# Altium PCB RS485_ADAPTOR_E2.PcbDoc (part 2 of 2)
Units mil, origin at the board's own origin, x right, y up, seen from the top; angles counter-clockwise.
Board outline 2150 x 1600 mil, 2 copper layers (Top Layer, Bottom Layer), stack 62 mil thick; 112 components, 44 nets, 256 pads, 64 vias.
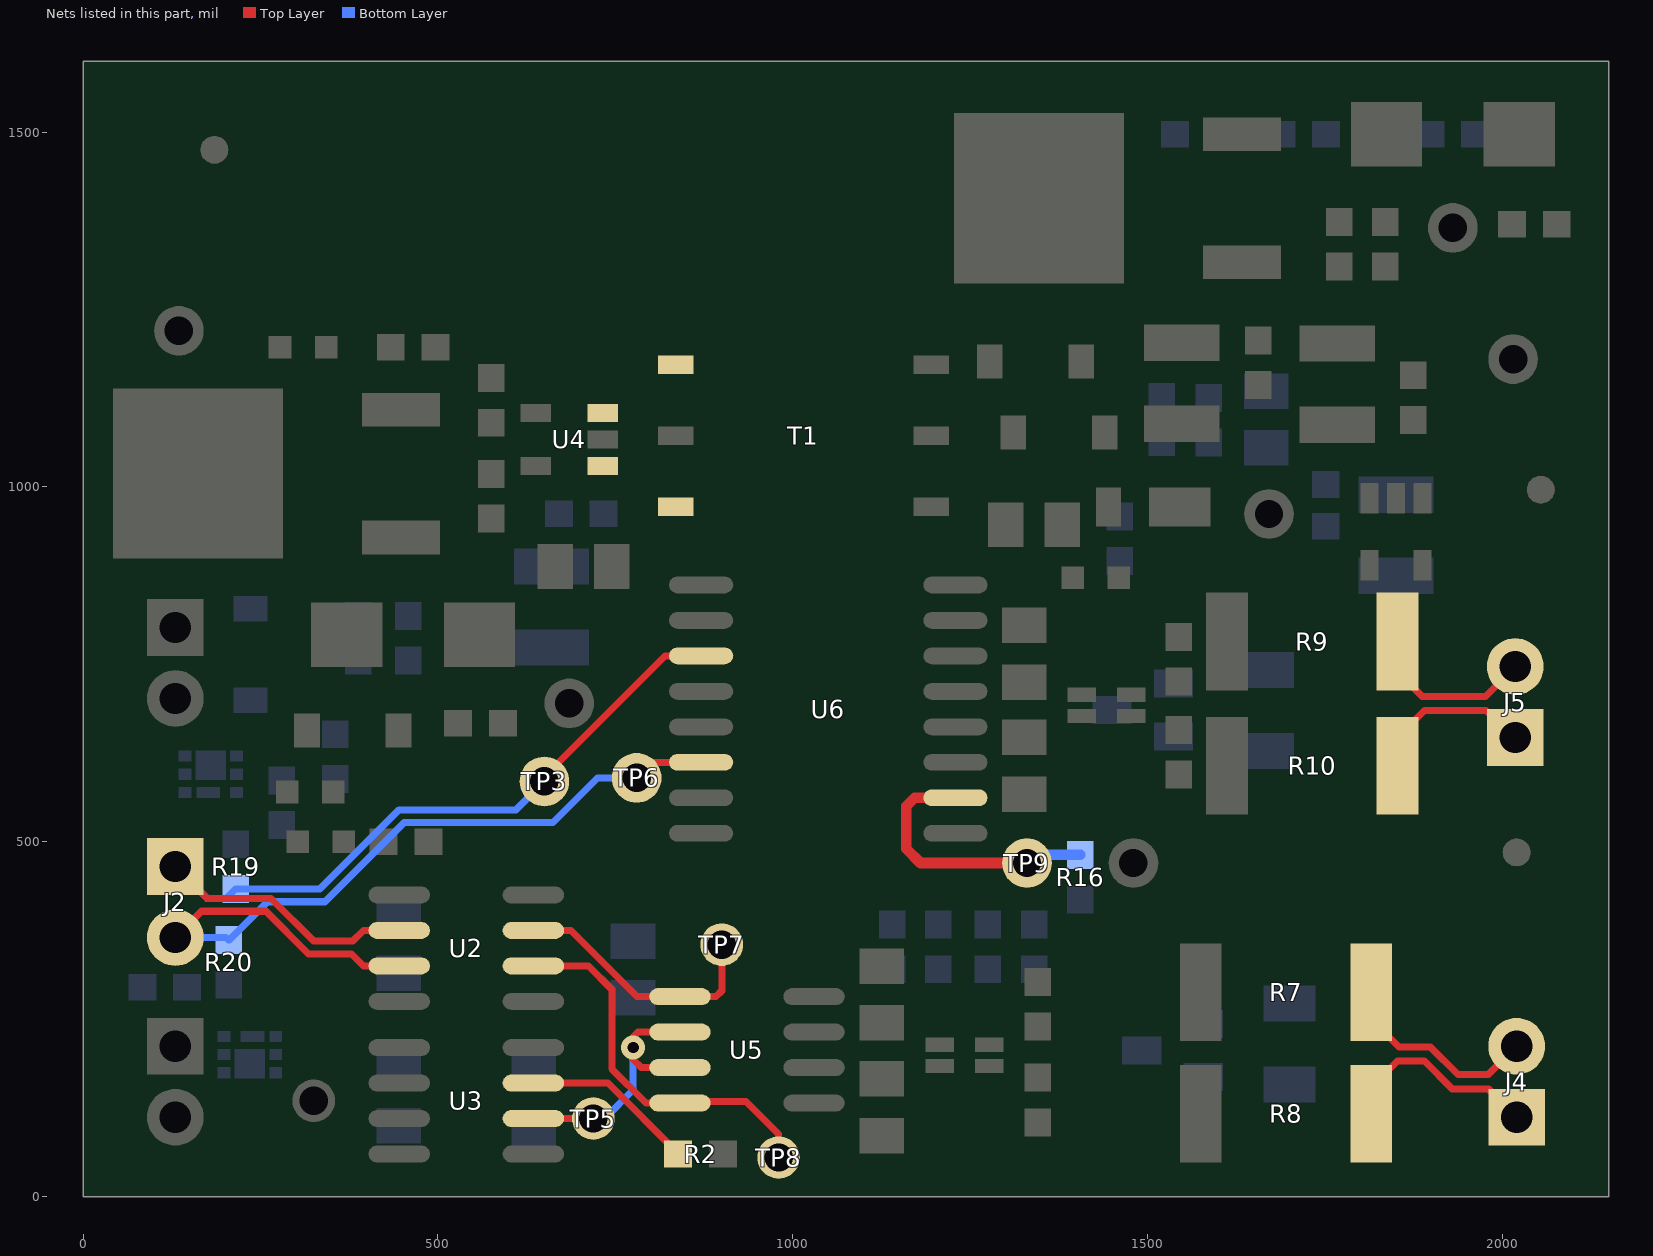
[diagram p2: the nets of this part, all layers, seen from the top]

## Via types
v1: diameter 34, hole 16, Top Layer to Bottom Layer, tented both sides, 64 vias

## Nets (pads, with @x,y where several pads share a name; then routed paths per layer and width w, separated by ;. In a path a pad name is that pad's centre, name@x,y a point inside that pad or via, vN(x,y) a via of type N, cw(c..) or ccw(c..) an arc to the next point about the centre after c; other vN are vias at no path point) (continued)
NetJ4_1: J4.1 R8.2 | length 298.3
  Top Layer w10: R8.2@1795.08,116.85 1795.08,133.93 1852,190.85 1890,190.85 1929,151.85 1980,151.85 J4.1@2020,111.85
NetJ4_2: J4.2 R7.2 | length 300.3
  Top Layer w10: R7.2@1795.08,287.85 1795.08,269.77 1854,210.85 1898.28,210.85 1937.28,171.85 1980,171.85 J4.2@2020,211.85
  Bottom Layer w10: J4.2@2019.91,211.76 J4.2@2020,211.85
NetJ5_1: J5.1 R10.2 | length 238.2
  Top Layer w10: R10.2@1852.08,607 1851,608.08 1851,645.85 1890,684.85 1977,684.85 J5.1@2015,646.85
  Bottom Layer w10: J5.1@2015,646.85 J5.1@2018,646.85
NetJ5_2: J5.2 R9.2 | length 240
  Top Layer w10: R9.2@1852.08,782 1852.08,739.77 1887,704.85 1976,704.85 J5.2@2018,746.85
NetR2_2: R2.2 U3.7 | length 246
  Top Layer w10: U3.7@634.49,160 739.54,160 838.5,61.04 R2.2@838.5,60
NetR16_1: R16.1 TP9.1 U6.10 | length 392.1
  Top Layer w15: U6.10@1229.13,561.85 1171.85,561.85 1160,550 1160,490 1180,470 TP9.1@1330,470
  Bottom Layer w15: TP9.1@1330,470 1341.5,481.5 R16.1@1405,481.5
NetT1_1: T1.1 U4.3
NetT1_3: T1.3 U4.1
NetTP5_1: TP5.1 U3.6 U5.2 U5.3 | length 388.4
  Top Layer w10: U3.6@634.49,110 TP5.1@703,110 ; U5.3@841.01,181.85 786.42,181.85 775,193.27 v1(775,210) 775,225 781.85,231.85 U5.2@841.01,231.85
  Bottom Layer w10: TP5.1@703,110 735,110 775,150 v1(775,210)
NetTP7_1: TP7.1 U2.7 U5.1 | length 372.5
  Top Layer w10: U2.7@634.49,375 687.57,375 780.72,281.85 U5.1@841.01,281.85 891.85,281.85 900,290 TP7.1@900,355
NetTP8_1: TP8.1 U2.6 U5.4 | length 544.1
  Top Layer w10: U2.6@634.49,325 712.12,325 745,292.12 745,180 793.15,131.85 U5.4@841.01,131.85 843.16,134 934,134 980,88 TP8.1@980,55
RX: J2.1 R19.1 TP3.1 U2.2 U6.3 | length 1270.3
  Top Layer w10: J2.1@130,465 175,420 265,420 325,360 380,360 395,375 U2.2@445.51,375 ; TP3.1@650,585 650,591.85 820,761.85 U6.3@870.87,761.85
  Bottom Layer w10: J2.1@130,465 175,420 201.5,420 R19.1@215,433.5 333.5,433.5 445,545 610,545 TP3.1@650,585
TX: J2.2 R20.1 TP6.1 U2.3 U6.6 | length 1208.7
  Top Layer w10: J2.2@130,365 167,402 257.54,402 317.54,342 378,342 395,325 U2.3@445.51,325 ; TP6.1@780,590 801.85,611.85 U6.6@870.87,611.85
  Bottom Layer w10: J2.2@130,365 201.5,365 R20.1@205,361.5 205.99,361.5 260,415.5 340.96,415.5 452.46,527 662,527 725,590 TP6.1@780,590
pads on no net: FID1.1 FID2.1 FID3.1 FID4.1 FID5.1 FID6.1 LBL1.0 U3.2 U6.11 U6.14 U8.4 U8.5

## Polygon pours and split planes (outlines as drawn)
GND_VDC on Top Layer "Bottom Layer-No Net" (solid, remove dead copper, pour order 45): 1375,1175 1605,1175 1615,1185 1710,1185 1720,1175 1810,1175 1840,1145 1920,1145 1940,1165 1940,1220 1930,1230 1565,1230 1555,1240 1555,1555 1545,1565 1215,1565 1200,1550 1200,1050 1260,1050 1280,1070 1280,1105 1290,1115 1340,1115 1350,1105 1350,1050 1325,1025 1325,995 1335,985 1410,985 1425,1000 1425,1035 1370,1170
DGND on Top Layer "Bottom Layer-No Net" (solid, remove dead copper, pour order 30): 295,1270 280,1285 50,1285 40,1275 40,789.85 69,760.85 164,760.85 180,745 190,735 190,660 165,635 90,635 70,615 70,570 85,555 210,555 220,565 220,640 250,670 290,670 315,645 320,645 380,705 465,705 475,715 475,815 460,830 360.73,830 285,905 285,1160 295,1170
NetC3_1 on Top Layer "Bottom Layer-No Net" (solid, remove dead copper, pour order 32): 477,1151.85 467,1141.85 398,1141.85 390,1133.85 390,1064.85 404,1050.85 517,1050.85 539,1028.85 539,1010.85 553,996.85 593,996.85 595,998.85 595,1110.85 593,1112.85 546,1112.85 524,1134.85 524,1213.85 517,1220.85 480,1220.85 477,1217.85
DGND on Top Layer "Bottom Layer-No Net" (solid, remove dead copper, pour order 34): 662,1200.85 571,1200.85 553,1182.85 553,1135.85 556,1132.85 602,1132.85 616,1118.85 616,1002.85 622,996.85 648,996.85 690,1038.85 690,1172.85
DGND on Top Layer "Bottom Layer-No Net" (solid, remove dead copper, pour order 38): 616,960.85 638,938.85 638,857.85 640,855.85 690,855.85 694,859.85 694,926.85 682,938.85 682,1041.85 660,1063.85 624,1063.85 616,1055.85
DVCC on Top Layer "Bottom Layer-No Net" (solid, remove dead copper, pour order 39): 704,833 720,849 720,926 726,932 771,932 771,871 782,860 782,826 724,768 724,682 701,659 667,659 640,686 640,720 617,743 574,743 539.5,777.5 558,796 558,833
+5V on Top Layer "Bottom Layer-No Net" (solid, remove dead copper, pour order 41): 379,952.85 369,942.85 369,862.85 380,851.85 502,851.85 522,871.85 522,938.85 508,952.85
DVCC on Top Layer "Bottom Layer-No Net" (solid, remove dead copper, pour order 33): 551.46,974.85 541,964.39 541,869.85 498,826.85 498,690.85 484,676.85 424,676.85 424,573.85 433,564.85 546,564.85 556,574.85 556,711.85 616,771.85 616,919.85 593,942.85 593,974.85
NetT1_3 on Top Layer "Bottom Layer-No Net" (solid, remove dead copper, pour order 37): 710,1041.85 710,966.85 735,941.85 857,941.85 860,944.85 860,982.85 858,984.85 774,984.85 748,1010.85 748,1041.85
NetT1_1 on Top Layer "Bottom Layer-No Net" (solid, remove dead copper, pour order 36): 711,1092.85 711,1125.85 778,1192.85 791,1205.85 849,1205.85 858,1196.85 860,1194.85 860,1162.85 860,1158.85 858,1156.85 851,1149.85 835,1149.85 786,1149.85 755,1118.85 754,1117.85 754,1092.85
+5V on Top Layer "Bottom Layer-No Net" (solid, remove dead copper, pour order 35): 750,1078.85 758,1078.85 770,1090.85 778,1098.85 791,1098.85 847,1098.85 860,1085.85 860,1061.85 860,1056.85 853,1049.85 843,1039.85 842,1038.85 818,1038.85 818,1037.85 796,1015.85 794,1013.85 777,1013.85 776,1013.85 768,1021.85 767,1022.85 767,1031.85 767,1043.85 756,1054.85 755,1055.85 748,1055.85 743.24,1055.85 733.24,1065.85 733,1066.09 733,1075.3 733,1076.85 735,1078.85
NetD5_2 on Top Layer "Bottom Layer-No Net" (solid, remove dead copper, pour order 42): 1179,1202.85 1168,1191.85 1168,1158.85 1176,1150.85 1294,1150.85 1303,1159.85 1303,1193.85 1294,1202.85
NetD7_2 on Top Layer "Bottom Layer-No Net" (solid, remove dead copper, pour order 43): 1207,985.85 1291,1069.85 1291,1101.85 1295,1105.85 1328,1105.85 1332,1101.85 1332,1049.85 1281,998.85 1264,998.85 1253,987.85 1253,948.85 1229,924.85 1181,924.85 1166,939.85 1166,983.85 1168,985.85
GND_VDC on Top Layer "Bottom Layer-No Net" (solid, remove dead copper, pour order 47): 1344,1031.85 1330,1017.85 1330,1003.85 1355,978.85 1355,895.85 1304,844.85 1304,784.85 1477,784.85 1491,770.85 1530,770.85 1530,809.85 1500,839.85 1427,839.85 1427,930.85 1442,945.85 1465,945.85 1469,949.85 1469,998.85 1447,1020.85 1416,1020.85 1405,1031.85
NetC18_2 on Top Layer "Bottom Layer-No Net" (solid, remove dead copper, pour order 49): 1811,1005.85 1750,1005.85 1717,972.85 1717,882.85 1719,880.85 1730,869.85 1744,869.85 1762,869.85 1769,876.85 1770,877.85 1770,886.85 1770,952.85 1780,962.85 1802,962.85 1814,962.85 1822,970.85 1822,1001.85 1818,1005.85
+6V_VDC on Top Layer "Bottom Layer-No Net" (solid, remove dead copper, pour order 44): 1387,1201.85 1384,1198.85 1384,1140.85 1417,1107.85 1417,1051.85 1425,1043.85 1455,1043.85 1471.08,1059.93 1609.06,1059.73 1642,1092.85 1667,1092.85 1724,1035.85 1815,1035.85 1837,1013.85 1837,962.85 1860,965 1860,1025 1900,1065 2040,1065 2050,1075 2050,1285 2035,1300 1885,1300 1865,1320 1720,1320 1695,1345 1580,1345 1580,1255 1595,1240 1960,1240 1980,1220 1980,1125 1970,1115 1725,1115 1675,1165 1625,1165 1585,1125 1480,1125 1427,1177.85 1427,1198.85 1424,1201.85
NetC20_1 on Top Layer "Bottom Layer-No Net" (solid, remove dead copper, pour order 46): 1585,1525 1585,1415 1595,1405 1650,1405 1685,1405 1690,1410 1705,1425 1705,1495 1705,1525 1695,1535 1605,1535 1595,1535 1585,1525
+5.0V_VDC on Top Layer "Bottom Layer-No Net" (solid, remove dead copper, pour order 57): 1559,615 1559,557 1505,515 1460,515 1450,505 1450,365 1435,350 1435,250 1420,235 1360,235 1350,245 1350,370 1385,405 1385,550 1400,565 1463,565 1490,594 1490,615
GND_VDC on Bottom Layer "Bottom Layer-No Net" (solid, remove dead copper, pour order 58): 2095,1555 2085,1565 1950,1565 1940,1555 1940,1460 1930,1450 1705,1450 1640,1385 1560,1385 1545,1400 1545,1550 1535,1560 1365,1560 1320,1515 1320,1000 1325,995 1400,995 1405,1000 1405,1330 1430,1355 2080,1355 2095,1370
+5.0V_VDC on Bottom Layer "Bottom Layer-No Net" (solid, remove dead copper, pour order 48): 1225,975 1210,960 1210,860 1257,849.85 1280,849.85 1335,905 1400,905 1435,940 1480,940 1485,945 1625,945 1630,950 1630,1015 1625,1020 1610,1020 1595,1005 1495,1005 1485,1015 1485,1100 1495,1110 1535,1110 1540,1115 1540,1195 1605,1260 2100,1260 2110,1270 2110,1315 2095,1330 1480,1330 1430,1280 1430,1000 1405,975
DGND on Bottom Layer "Bottom Layer-No Net" (solid, remove dead copper, pour order 55): 560,770 595,805 790,805 830,845 830,1155 815,1170 715,1170 695,1150 695,955 685,945 640,945 635,950 635,1155 605,1185 55,1185 45,1195 45,1280 55,1290 865,1290 890,1265 890,520 875,505 705,505 700,510 700,620 685,635 645,635 605,595 575,595 490,680 295,680 285,690 285,740 290,745 335,745 360,770
+5.0V_VDC on Bottom Layer "Bottom Layer-No Net" (solid, remove dead copper, pour order 52): 1218,955.85 1209,946.85 1209,563.85 1255,517.85 1372,517.85 1372,541.85 1308,605.85 1308,910.85 1263,955.85
NetC19_2 on Bottom Layer "Bottom Layer-No Net" (solid, remove dead copper, pour order 51): 1765,985 1735,985 1710,1010 1695,1025 1620,1025 1515,1025 1500,1040 1500,1080 1540,1080 1735,1080 1770,1045 1770,990 1765,985
NetC18_2 on Bottom Layer "Bottom Layer-No Net" (solid, pour order 50): 1773,962.85 1776,959.85 1776,918.85 1793,901.85 1903,901.85 1907,897.85 1907,839.85 1893,825.85 1768,825.85 1730,863.85 1730,962.85
GND_VDC on Bottom Layer "Bottom Layer-No Net" (solid, remove dead copper, pour order 54): 1590,1220 1605,1235 1960,1235 1995,1200 1995,1050 1915,970 1810,970 1800,980 1800,1040 1735,1105 1600,1105 1590,1115
+5.0V_VDC on Bottom Layer "Bottom Layer-No Net" (solid, remove dead copper, pour order 56): 645,405 635,395 635,150 705,150 735,180 735,235 730,240 690,240 685,245 685,305 705,325 820,325 830,315 830,295 880,245 1310,245 1320,235 1320,100 1330,90 1405,90 1420,105 1420,340 1415,345 865,345 805,405
NetD11_2 on Bottom Layer "Bottom Layer-No Net" (solid, remove dead copper, pour order 31): 76,649 180,649 197,666 197,732 180,751 81,751 65,735 65,660
+5V on Bottom Layer "Bottom Layer-No Net" (solid, remove dead copper, pour order 40): 209,807 356,807 360,802 362.46,797.85 528,797.85 592,861.85 761,861.85 809,909.85 809,1087.48 793.63,1102.85 729,1102.85 715,1088.85 715,1060.85 715,1053.85 715,936.85 701,922.85 382,922.85 185,923 184,835
GND_VDC on Bottom Layer "Bottom Layer-No Net" (solid, remove dead copper, pour order 53): 1342,880.85 1329,867.85 1329,626.85 1380,575.85 1434,575.85 1479,620.85 1479,767.85 1538,826.85 1579,826.85 1579,787.85 1595,771.85 1595,495 1540,440 1375,440 1355,420 1050,420 1035,405 1035,375 1045,365 1415,365 1440,340 1440,95 1425,80 1310,80 1300,90 1300,205 1280,225 870,225 790,305 765,305 765,245 800,210 800,155 735,90 695,90 685,80 685,45 700,30 1905,30 1945,70 1944,770.85 1914,800.85 1756,800.85 1708,848.85 1708,893.85 1701,900.85 1620,900.85 1609,916 1545,916 1482,857 1430,856.85 1406,880.85

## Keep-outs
Keep-Out Layer:
  lines w1: 30,25 2120,25 2120,1575 30,1575 30,25
  text ".Layer_Name" at 569,-677.64 h60

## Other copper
Top Layer:
  text ".Layer_Name" at 569,-677.64 h60
Bottom Layer:
  pour cut-out: 1493.18,287.67 1632.33,287.67 1640,280 1640,130 1619.57,109.57 1506.19,109.57 1490.05,125.71 1490.05,157.99 1531.84,199.78 1531.84,215.7 1493.18,254.37
  pour cut-out: 1760,315 1760,115 1754.57,109.57 1619.57,109.57 1619.57,274.92 1620,300 1635,315
  pour cut-out: 1579,787.85 1722.15,787.85 1730,780 1730,590 1720,580 1590,580 1580,590 1580,786.85
  text ".Layer_Name" at 569,-677.64 h60

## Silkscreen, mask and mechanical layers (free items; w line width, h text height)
Top Overlay:
  lines w6: 425,560 425,605 ; 1195,1253 1255,1253 1278,1230 ; 1465,1253.85 1479,1253.85 1486.28,1246.57 1486.28,1237.05 ; 1683.2,1234.83 1694.37,1246 1850.15,1246 ; 1878,1297 1943,1297 ; 1890,544 1891,544 1900,535 ; 1962,1337 1963,1337 1970,1330 2062,1330 2067,1325 ; 2111,1372 2127,1388 2127,1409 ; 1943,1297 1935,1289 1935,1305 1943,1297
  text "ISE3013" at 1578,453 h50
  text "REV:E2" at 1600,387 h40
  text ".layer_Name" at 568,-679.15 h60
Bottom Overlay:
  text ".Layer_Name" at 569,-677.64 h60
Top Paste:
  text ".Layer_Name" at 569,-677.64 h60
Bottom Paste:
  text ".Layer_Name" at 569,-677.64 h60
Top Solder:
  text ".Layer_Name" at 569,-677.64 h60
  text ".Layer_Name" at 569,-677.64 h60
Bottom Solder:
  text ".Layer_Name" at 569,-677.64 h60
Drill Guide:
  text ".Layer_Name" at 569,-677.64 h60
M1 Board Outline:
  the board outline again, w6
  text "OUTLINE" at 683,-681 h60
M2 Board Dimensions:
  rectangle: 116.5,-229.65 491.5,-104.65
  rectangle: -8.5,-104.65 116.5,20.35
  lines w7: -8.5,-104.65 991.5,-104.65 ; 116.5,-229.65 116.5,20.35 ; 241.5,-229.65 241.5,20.35 ; 491.5,-229.65 491.5,20.35 ; 741.5,-229.65 741.5,20.35 ; -8.5,-229.65 -8.5,20.35 991.5,20.35 991.5,-229.65 -8.5,-229.65
  lines w10: -8.5,-294.65 -8.5,-274.65 ; 51.5,-304.65 -8.5,-284.65 ; 51.5,-264.65 -8.5,-284.65 ; 215.58,-284.65 -8.5,-284.65 ; 767.42,-284.65 991.5,-284.65 ; 931.5,-304.65 991.5,-284.65 ; 931.5,-264.65 991.5,-284.65 ; 991.5,-294.65 991.5,-274.65
  text "1000 (mil)" at 225.58,-320.64 h60
M3 3D STEP Top:
  text ".Layer_Name" at 569,-677.64 h60
M4 3D STEP Bottom:
  text ".Layer_Name" at 569,-677.64 h60
M5 Assembly Top:
  lines w7.87: 19.76,315 19.76,515 ; 74.88,315 74.88,515 ; 185.12,315 185.12,515 ; 188.21,569.96 213.21,569.96 ; 208.74,315 208.74,515 ; 208.74,344.53 257.95,344.53 ; 208.74,385.47 257.95,385.47 ; 208.74,444.53 257.95,444.53 ; 208.74,485.47 257.95,485.47 ; 213.21,544.96 213.21,594.96 ; 228.43,446.5 228.43,485.47 ; 229,344.53 229,385.47 ; 236.3,319 236.3,344.13 ; 236.3,387.44 236.3,442.56 ; 236.3,485.87 236.3,515 ; 238.21,569.96 263.21,569.96 ; 248,385.47 248,348.18 248.11,348.07 ; 248.11,446.5 248.11,485.47 ; 295,445 320,445 345,470 345,420 322,443 ; 308.58,554.25 331.42,554.25 ; 308.58,585.75 331.42,585.75 ; 321,425 321,465 ; 323.58,484.25 346.42,484.25 ; 323.58,515.75 346.42,515.75 ; 345,445 370,445 ; 213.21,569.96 238.21,544.96 238.21,594.96 214,570.75 213.21,569.96 ; 2.05,315 257.95,315 257.95,515 2.05,515 2.05,315
  lines w10: -300,-749.32 6300,-749.32 ; -300,-545.98 6302,-545.98 ; -300,-342.65 -300,-952.65 3705,-952.65 6302,-952.65 6302,-342.65 -299.5,-342.65 -299.5,-952.65 1276,-952.65 ; 2165,-952.65 2165,-342.65 ; 3432,-545.98 3432,-342.65 ; 4272,-545.98 4272,-342.65 ; 4894,-959.15 4894,-756.32
  text "D2" at 356,554 h36
  text "ISE3013" at 892,414 h60
  text "J2" at 149,393 h36 r90
  text "D4" at 305,373 h36
  text "COMPONENTS MARKED 'DNP' SHOULD NOT BE POPULATED." at 1145.5,-137.65 h60
  text "ASSEMBLY VARIANT:" at 1145,-253.15 h60
  text ".VariantName" at 2181,-253.15 h60
  text "PCB VIEWED FROM TOP SIDE" at -236.5,-474.82 h60
  text "BOARD #:" at 2240,-474.82 h60
  text ".PRJ_Number" at 2785.5,-474.82 h60
  text "REV:" at 3630,-474.82 h60
  text "E2" at 3921.5,-474.82 h60
  text "SVN REV:" at 4468,-474.82 h60
  text ".VersionControl_RevNumber" at 4974,-474.82 h60
  text ".Layer_Name" at 569,-677.64 h60
  text "LAYER NAME =" at -236.5,-677.82 h60
  text "ISE3013" at 2407,-684.15 h60
  text "PLOT NAME =" at -236.5,-883.49 h60
  text ".plot_File_Name" at 569,-883.49 h60
  text "GENERATED    :" at 2242,-883.49 h60
  text ".Print_Date" at 3111.5,-883.49 h60
  text ".Print_Time" at 3840.5,-883.49 h60
  text "TEXAS INSTRUMENTS" at 5105,-883.49 h60
M6 Assembly Bottom:
  lines w10: -299.5,-545.98 6302.5,-545.98 ; -297.5,-749.32 6302.5,-749.32 ; 1108.5,-959.15 1108.5,-756.32 ; 1730.5,-545.98 1730.5,-342.65 ; 2570.5,-545.98 2570.5,-342.65 ; 3837.5,-952.65 3837.5,-342.65 ; 4726.5,-952.65 6302,-952.65 6302,-342.65 -299.5,-342.65 -299.5,-952.65 2297.5,-952.65 6302.5,-952.65 6302.5,-342.65
  text "COMPONENTS MARKED 'DNP' SHOULD NOT BE POPULATED." at 4857,-137.65 h60
  text ".VariantName" at 3821.5,-253.15 h60
  text "ASSEMBLY VARIANT:" at 4857.5,-253.15 h60
  text ".VersionControl_RevNumber" at 1028.5,-474.82 h60
  text "SVN REV:" at 1534.5,-474.82 h60
  text "E2" at 2081,-474.82 h60
  text "REV:" at 2372.5,-474.82 h60
  text ".PRJ_Number" at 3217,-474.82 h60
  text "BOARD #:" at 3762.5,-474.82 h60
  text "PCB VIEWED FROM BOTTOM SIDE" at 6239,-474.82 h60
  text ".Layer_Name" at 5433.5,-677.64 h60
  text "LAYER NAME =" at 6239,-677.82 h60
  text "ISE3013" at 3595.5,-684.15 h60
  text "TEXAS INSTRUMENTS" at 897.5,-883.49 h60
  text ".Print_Time" at 2162,-883.49 h60
  text ".Print_Date" at 2891,-883.49 h60
  text "GENERATED    :" at 3760.5,-883.49 h60
  text ".plot_File_Name" at 5433.5,-883.49 h60
  text "PLOT NAME =" at 6239,-883.49 h60
M7 LPKF Text Top:
  lines w10: -300.5,-546.48 6301.5,-546.48 ; -298.5,-749.82 6301.5,-749.82 ; 1107.5,-959.65 1107.5,-756.82 ; 1729.5,-546.48 1729.5,-343.15 ; 2569.5,-546.48 2569.5,-343.15 ; 3836.5,-953.15 3836.5,-343.15 ; 4725.5,-953.15 6301,-953.15 6301,-343.15 -300.5,-343.15 -300.5,-953.15 2296.5,-953.15 6301.5,-953.15 6301.5,-343.15
  text "COMPONENTS MARKED 'DNP' SHOULD NOT BE POPULATED." at 6094,-137.15 h60
  text ".VariantName" at 5050,-253.15 h60
  text "ASSEMBLY VARIANT:" at 6089,-253.15 h60
  text ".VersionControl_RevNumber" at 1027.5,-475.32 h60
  text "SVN REV:" at 1533.5,-475.32 h60
  text ".PCB_Rev" at 2080,-475.32 h60
  text "REV:" at 2371.5,-475.32 h60
  text ".PRJ_Number" at 3216,-475.32 h60
  text "BOARD #:" at 3761.5,-475.32 h60
  text "Bottom Overlay" at 5632.5,-673.99 h60
  text "TIDA-00127-PRPS" at 3267,-679.15 h60
  text "TEXAS INSTRUMENTS" at 896.5,-883.99 h60
  text ".Print_Time" at 2161,-883.99 h60
  text ".Print_Date" at 2890,-883.99 h60
  text "GENERATED    :" at 3759.5,-883.99 h60
  text "Bottom Overlay" at 5432.5,-883.99 h60
  text "PLOT NAME =" at 6238,-883.99 h60
M9 Title Sheet:
  drawing of 56 lines, arcs and shapes, not listed
  text "1" at 731.84,8217.35 h70
  text "2" at 3227.5,8217.35 h70
  text "3" at 5716.84,8217.35 h70
  text "5" at 10722.5,8217.35 h70
  text "6" at 13227.5,8217.35 h70
  text "A" at -424.5,7074.35 h70
  text "A" at 14375.5,7074.35 h70
  text "B" at -424.5,4694.35 h70
  text "B" at 14375.5,4694.35 h70
  text "C" at -424.5,2319.35 h70
  text "C" at 14375.5,2319.35 h70
  text "PROJECT TITLE:" at 11335.5,458.35 h45
  text "RS485_COMMS" at 11385.5,325.02 h70
  text "DESIGNED FOR:" at 11335.5,157.35 h45
  text ".PRJ_Customer" at 11385.5,17.35 h70
  text "D" at -424.5,-50.65 h70
  text "D" at 14375.5,-50.65 h70
  text "FILE NAME:" at 11335.5,-142.65 h45
  text "ISE3013" at 11385.5,-262.65 h70
  text "Texas Instruments (TI) and/or its licensors do not warrant the accuracy or completeness of this specification" at 6366,-424.49 h45
  text "ENGINEER:" at 11335.5,-432.65 h45
  text "LAYOUT BY:" at 12840.5,-432.65 h45
  text "or any information contained therein. TI and/or its licensors do not warrant that this design will meet" at 6321.01,-537.15 h45
  text "Sreenivasa Kallikuppa" at 11341,-587.15 h70
  text ".PCB_Layout" at 12846.5,-587.15 h70
  text "the specifications, will be suitable for your application or fit for any particular purpose, or will operate in" at 6321.01,-649.82 h45
  text "ALTIUM DESIGNER VERSION:" at 12840.5,-742.65 h45
  text "an implementation. TI and/or its licensors do not warrant that the design is production worthy. You should" at 6321.01,-762.48 h45
  text "completely validate and test your design implementation to confirm the system functionality for your application." at 6366,-875.15 h45
  text ".print_Scale" at 11385.5,-875.98 h70
  text ".Application_BuildNumber" at 12891,-875.98 h70
  text "1" at 731.84,-1082.65 h70
  text "2" at 3227.5,-1082.65 h70
  text "3" at 5716.84,-1082.65 h70
  text "4" at 8223.51,-1082.65 h70
  text "5" at 10722.5,-1082.65 h70
  text "6" at 13227.5,-1082.65 h70
M10 Fab Notes:
  drawing of 220 lines, arcs and shapes, not listed
  text "DESIGN INFORMATION" at 12373.02,6990.85 h60
  text "(REFER ALSO ARRAY/PANEL PROFILING INFORMATION)" at 12011.46,6829.14 h60
  text "BOARD SIZE" at 11325.46,6824.85 h60
  text "2150MIL" at 11727,6700.85 h60
  text "1600MIL" at 12457,6700.85 h60
  text "X" at 12293.46,6697.03 h60
  text "Number of Layers :" at 11728.46,6499.85 h60
  text "2" at 12823.27,6489.85 h60
  text "MIN. TRACK WIDTH:" at 11728.46,6360.85 h60
  text "10" at 12824.7,6360.85 h60
  text "MIL" at 12979.46,6360.85 h60
  text "MIN. CLEARANCE:" at 11728.46,6228.85 h60
  text "8" at 12824.7,6228.85 h60
  text "MIL" at 12979.46,6228.85 h60
  text "MIN. VIA PAD SIZE:" at 11728.46,6096.85 h60
  text "34" at 12794.71,6096.85 h60
  text "MIL" at 12979.46,6096.85 h60
  text "0.05mm (2MIL)" at 12423.46,5955.14 h60
  text "MINIMUM ANNULAR RING" at 11399.23,5950.86 h60
  text "EXTERNAL" at 13131.46,5950.86 h60
  text "PER" at 11599.23,5832.85 h60
  text "IPC-D-275 CLASS 2 LEVEL C" at 11819.23,5832.85 h60
  text "MIL, HOLES" at 13307.46,5720.56 h60
  text "+/-" at 12915,5719.85 h60
  text "+/-" at 13769,5719.85 h60
  text "REGISTRATION TOLERANCES:" at 11399.23,5714.85 h60
  text "METAL" at 12599,5714.85 h60
  text "5" at 13175.2,5714.85 h60
  text "3" at 14008.2,5714.85 h60
  text "MIL" at 14124.46,5714.85 h60
  text "MATERIAL:" at 11324.46,5505.39 h60
  text "FR-4 High Tg" at 12310.9,5365.06 h60
  text "X" at 11596,5356.85 h60
  text "FR-408" at 11745.46,5356.49 h60
  text "OTHER" at 13233.46,5356.49 h60
  text "63 MIL (1.6mm) +/-10%" at 12065.56,5193.77 h60
  text "THICKNESS:" at 11399.23,5189.49 h60
  text "X" at 11937.4,5189.49 h60
  text "OTHER" at 13350.46,5189.49 h60
  text "TOLERANCE:" at 11399.23,5031.49 h60
  text "X" at 12238.53,5031.49 h60
  text "ANSI IPC-6012 TYPE 3 CLASS 2" at 12425.48,5031.49 h60
  text "OTHER +/-" at 12425.46,4875.49 h60
  text "BOW & TWIST:" at 11399.23,4718.49 h60
  text "X" at 12238.53,4718.49 h60
  text "ANSI IPC-6012 TYPE 3 CLASS 2" at 12425.48,4718.49 h60
  text "OTHER +/-" at 12425.46,4559.98 h60
  text "COPPER THICKNESS (FINISHED):" at 11324.46,4424.49 h60
  text "1.4MIL (1oz)" at 12204.46,4271.77 h60
  text "2MIL (1.4oz)" at 12971.46,4271.77 h60
  text "2.8MIL (2oz)" at 13698.46,4271.77 h60
  text "OUTER:" at 11681.46,4267.49 h60
  text "X" at 12076,4266.85 h60
  text "1.4MIL (1oz)" at 12204.46,4114.77 h60
  text "2.8MIL (2oz)" at 12971.46,4114.77 h60
  text "N/A" at 13698,4115.14 h60
  text "INNER SIGNAL:" at 11392.38,4110.49 h60
  text "DRILLING:" at 11324.46,3971.49 h60
  text "REFERENCE:" at 11399.23,3854.49 h60
  text "X" at 12047.46,3854.49 h60
  text "AS SHOWN" at 12234.46,3854.49 h60
  text "X" at 12948.46,3854.49 h60
  text "NC_DRILL FILES" at 13085.46,3854.49 h60
  text "PTH MIN COPPER THICKNESS:" at 11399.23,3696.49 h60
  text "X" at 12749.46,3696.49 h60
  text "1MIL" at 12886.46,3696.49 h60
  text "OTHER" at 13383.46,3696.49 h60
  text "BOARD FINISH:" at 11324.46,3537.49 h60
  text "SILKSCREEN:" at 11479.68,3419.49 h60
  text "X" at 12428.46,3419.49 h60
  text "TOP" at 12554.46,3419.49 h60
  text "X" at 12938.46,3419.49 h60
  text "BOTTOM" at 13065.46,3419.49 h60
  text "SILKSCREEN COLOR:" at 11479.68,3252.49 h60
  text "X" at 12427.42,3252.49 h60
  text "WHITE" at 12554.46,3252.49 h60
  text "OTHER" at 13065.46,3252.49 h60
  text "SOLDER RESIST COLOR:" at 11479.68,3082.49 h60
  text "X" at 12047.42,2923.29 h60
  text "GREEN" at 12174.46,2923.29 h60
  text "BLUE" at 12765.46,2923.29 h60
  text "OTHER" at 13303.46,2923.29 h60
  text "IMMERSION GOLD (ENIG)" at 12385.46,2734.77 h60
  text "ENEPIG" at 13723,2731.49 h60
  text "SURFACE FINISH:" at 11324.46,2730.49 h60
  text "X" at 12198.51,2730.49 h60
  text "IMM. TIN/SILVER OR EQUIV" at 11654,2573.49 h60
  text "OTHER" at 13085.46,2573.49 h60
  text "ARRAY/PANEL:" at 11324.46,2394.49 h60
  text "CUT AND TRIM PER MECH LAYER 1" at 12385.46,2390.2 h60
  text "N.C. ROUTE" at 12385.46,2238.49 h60
  text "X" at 13064.46,2238.49 h60
  text "V. SCORE" at 13251.46,2238.49 h60
  text "CERTIFICATION:" at 11324.46,2101.49 h60
  text "MATERIALS AND WORKMANSHIP FOR ALL PCBS" at 12049.46,2101.49 h60
  text "TO MEET OR EXCEED THE REQUIREMENTS OF:" at 12049.46,2003.49 h60
  text "X" at 11675.96,1866.99 h60
  text "ANSI IPC-A-600F CLASS ->" at 11814.96,1866.99 h60
  text "X" at 13454.02,1866.99 h60
  text "2" at 13572.96,1866.99 h60
  text "1" at 13257.96,1865.49 h60
  text "3" at 13926.96,1865.49 h60
  text "X" at 11678.02,1707.49 h60
  text "UL 94V-0" at 11814.96,1707.49 h60
  text "X" at 12490.02,1707.49 h60
  text "RoHS" at 12626.96,1707.49 h60
  text "OTHER" at 13271.36,1707.49 h60
  text "PER ORDER" at 13668.42,1707.49 h60
  text "ADDITIONAL REQUIREMENTS:" at 11324.46,1566.49 h60
  text "NO" at 13843.46,1462.85 h60
  text "VIA TENTING:" at 12704,1461.85 h60
  text "X" at 13296.46,1459.99 h60
  text "YES" at 13421.96,1459.99 h60
  text "MICROSECTION:" at 11399.23,1451.49 h60
  text "YES" at 12304.96,1451.49 h60
  text "REQUIRED" at 13166.46,1295.35 h60
  text "BARE BOARD ELEC. TEST:" at 11399.23,1292.49 h60
  text "NONE" at 12704.96,1292.49 h60
  text "X" at 13039.46,1292.49 h60
  text "PER ORDER" at 13758.46,1292.49 h60
  text "MANUFACTURER'S UL:" at 11399.23,1135.49 h60
  text "RAIL" at 12564.96,1131.2 h60
  text "METAL" at 13056.77,1131.2 h60
  text "X" at 13432,1130.85 h60
  text "SILK" at 13568.46,1131.2 h60
M11 Gerber Information:
  lines w10: -300,-749.32 6300,-749.32 ; -300,-545.98 6302,-545.98 ; -300,-342.65 -300,-952.65 3705,-952.65 6302,-952.65 6302,-342.65 -299.5,-342.65 -299.5,-952.65 1276,-952.65 ; 2165,-952.65 2165,-342.65 ; 3432,-545.98 3432,-342.65 ; 4272,-545.98 4272,-342.65 ; 4894,-959.15 4894,-756.32
  text "BOARD #:" at 2241,-474.15 h60
  text "ALL ARTWORK VIEWED FROM TOP SIDE" at -236.5,-474.82 h60
  text ".PRJ_Number" at 2786,-475.15 h60
  text "REV:" at 3630,-474.82 h60
  text "SVN REV:" at 4468,-474.82 h60
  text ".VersionControl_RevNumber" at 4974,-474.82 h60
  text "E2" at 3922,-476.15 h60
  text "LAYER NAME =" at -236.5,-677.64 h60
  text "ISE3013" at 2407,-679.15 h60
  text "PLOT NAME =" at -236.5,-883.49 h60
  text ".plot_File_Name" at 569,-883.49 h60
  text "GENERATED    :" at 2242,-883.49 h60
  text ".Print_Date" at 3111.5,-883.49 h60
  text ".Print_Time" at 3840.5,-883.49 h60
  text "TEXAS INSTRUMENTS" at 5105,-883.49 h60
M12 Stackup:
  lines w6: 11353,7656.18 14214,7656.18 ; 11353,7764.68 14214,7764.68 ; 11293,7156.85 ccw(c11328,7156.85) 11328,7121.85 14239,7121.85 ccw(c14239,7156.85) 14274,7156.85 14274,7883.85 ccw(c14239,7883.85) 14239,7918.85 11328,7918.85 ccw(c11328,7883.85) 11293,7883.85 11293,7156.85
  text "The Stackup Legend below this is static." at 11597.5,8055.35 h60
  text "If you change the stackup, update the Legend." at 11607.5,7965.35 h60
  text "Layer Stack Up Detail for: RS485_ADAPTOR.PcbDoc" at 11353,7797.57 h59
  text "Layer" at 11353,7724.18 h25
  text "Gerber" at 12353.47,7724.18 h25
  text "Copper" at 13014.92,7724.18 h25
  text "Dielectric" at 13717.19,7724.18 h25
  text "Name" at 11353,7674.18 h25
  text "Document" at 12353.47,7674.18 h25
  text "Thickness" at 13014.92,7674.18 h25
  text "Material" at 13717.19,7674.18 h25
  text "Top Solder Mask" at 11353,7578.47 h35
  text "(.GTS)" at 12353.47,7578.47 h35
  text "Solder Resist" at 13717.19,7578.47 h35
  text "Top Layer" at 11353,7478.84 h35
  text "(.GTL)" at 12353.47,7478.84 h35
  text "1.4mil" at 13014.92,7478.84 h35
  text "FR-4" at 13717.19,7429.03 h35
  text "Bottom Layer" at 11353,7379.22 h35
  text "(.GBL)" at 12353.47,7379.22 h35
  text "1.4mil" at 13014.92,7379.22 h35
  text "Bottom Solder Mask" at 11353,7279.59 h35
  text "(.GBS)" at 12353.47,7279.59 h35
  text "Solder Resist" at 13717.19,7279.59 h35
M13 Component Bodies Top:
  text ".Layer_Name" at 569,-677.64 h60
M14 Component Bodies Bottom:
  text ".Layer_Name" at 569,-677.64 h60
M15 Courtyards Top:
  text ".Layer_Name" at 569,-677.64 h60
M16 Courtyards Bottom:
  text ".Layer_Name" at 569,-677.64 h60
Drill Drawing:
  text ".legend" at 2735,1106.85 h60
  text "Drill Table" at 2752,957.85 h60
  text "DRILL TOLERANCES:" at 2746,802.85 h60
  text "FOR PTH +/-3MILS" at 3835,798.85 h60
  text "FOR NPTH +/-2MILS" at 3831,661.85 h60
  text ".Layer_Name" at 569,-677.64 h60

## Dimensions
0,1600 to 2150,1600 on Drill Drawing
2150,1600 to 2150,0 on Drill Drawing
